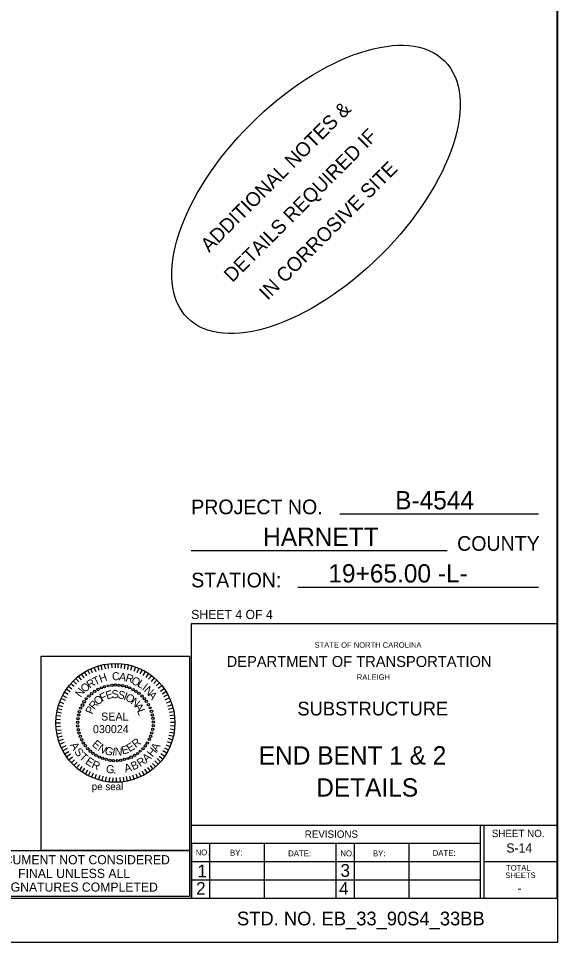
# Model space of a CAD drawing. Extents: x -41 to 251, y -169 to 237.
# Drawn here: x 58.79 to 75.65, y -168.52 to -139.61 of the extents above; entities that cross this region are included whole.
import ezdxf

# ---------------------------------------------------------------- set-up
doc = ezdxf.new("R2010")
doc.units = 0
for name, color, linetype in [('Peseal', 7, 'Continuous'), ('Plan Sheet CELL', 7, 'Continuous'), ('Plot Shape CELL', 7, 'Continuous'), ('Sheet Sticker Exception Certification CELL', 7, 'Continuous'), ('Subtitle Text', 7, 'Continuous'), ('Text', 7, 'Continuous'), ('Title Text', 7, 'Continuous'), ('User Information Notes', 7, 'Continuous'), ('User Information Notes CELL', 7, 'Continuous')]:
    doc.layers.add(name, color=color, linetype=linetype)

msp = doc.modelspace()

# ---------------------------------------------------------------- linework, layer by layer
at = {"layer": 'Peseal'}
for p, q in [((61.31, -160.006), (61.265, -159.863)), ((61.408, -159.98), (61.373, -159.836)), ((61.507, -159.953), (61.48, -159.81)), ((61.605, -159.944), (61.587, -159.801)), ((61.713, -159.926), (61.704, -159.783)), ((61.82, -159.926), (61.82, -159.783)), ((61.9, -159.926), (61.909, -159.783)), ((61.999, -159.935), (62.017, -159.792)), ((62.106, -159.953), (62.124, -159.81)), ((62.205, -159.971), (62.231, -159.828)), ((62.303, -159.997), (62.339, -159.854)), ((60.836, -160.23), (60.755, -160.114)), ((60.925, -160.176), (60.854, -160.051)), ((61.015, -160.123), (60.952, -159.997)), ((61.104, -160.078), (61.051, -159.953)), ((61.212, -160.042), (61.158, -159.908)), ((62.401, -160.024), (62.455, -159.89)), ((62.5, -160.069), (62.562, -159.935)), ((62.598, -160.114), (62.661, -159.98)), ((62.688, -160.158), (62.759, -160.033)), ((62.777, -160.221), (62.858, -160.096)), ((60.532, -160.507), (60.424, -160.418)), ((60.603, -160.436), (60.496, -160.328)), ((60.675, -160.364), (60.585, -160.257)), ((60.755, -160.293), (60.666, -160.185)), ((62.858, -160.275), (62.947, -160.167)), ((62.947, -160.346), (63.036, -160.239)), ((63.019, -160.409), (63.117, -160.311)), ((63.09, -160.489), (63.198, -160.391)), ((60.344, -160.758), (60.219, -160.686)), ((60.407, -160.668), (60.281, -160.588)), ((60.46, -160.588), (60.353, -160.507)), ((63.153, -160.561), (63.269, -160.472)), ((63.224, -160.65), (63.341, -160.57)), ((63.278, -160.731), (63.394, -160.659)), ((60.21, -161.044), (60.076, -160.99)), ((60.254, -160.946), (60.12, -160.883)), ((60.299, -160.856), (60.165, -160.785)), ((63.332, -160.82), (63.457, -160.758)), ((63.376, -160.919), (63.502, -160.856)), ((63.421, -161.017), (63.555, -160.964)), ((60.147, -161.241), (60.013, -161.205)), ((60.174, -161.142), (60.04, -161.098)), ((63.457, -161.116), (63.591, -161.071)), ((63.484, -161.214), (63.618, -161.178)), ((63.502, -161.312), (63.645, -161.286)), ((60.102, -161.545), (59.959, -161.536)), ((60.111, -161.438), (59.977, -161.42)), ((60.129, -161.339), (59.986, -161.312)), ((63.52, -161.411), (63.663, -161.393)), ((63.528, -161.509), (63.672, -161.5)), ((60.102, -161.652), (59.959, -161.652)), ((60.102, -161.76), (59.959, -161.769)), ((60.12, -161.867), (59.977, -161.885)), ((63.528, -161.831), (63.672, -161.849)), ((63.537, -161.617), (63.681, -161.617)), ((63.537, -161.724), (63.681, -161.733)), ((60.129, -161.965), (59.995, -161.992)), ((60.156, -162.064), (60.013, -162.1)), ((60.183, -162.162), (60.049, -162.207)), ((63.466, -162.126), (63.609, -162.171)), ((63.493, -162.028), (63.636, -162.064)), ((63.511, -161.93), (63.654, -161.957)), ((60.219, -162.261), (60.085, -162.314)), ((60.263, -162.359), (60.129, -162.422)), ((60.308, -162.449), (60.174, -162.52)), ((63.35, -162.422), (63.484, -162.484)), ((63.394, -162.332), (63.528, -162.386)), ((63.439, -162.225), (63.573, -162.279)), ((60.362, -162.547), (60.237, -162.618)), ((60.415, -162.627), (60.299, -162.708)), ((60.478, -162.717), (60.362, -162.806)), ((63.189, -162.681), (63.305, -162.771)), ((63.242, -162.601), (63.367, -162.681)), ((63.305, -162.511), (63.43, -162.583)), ((60.541, -162.797), (60.442, -162.887)), ((60.621, -162.869), (60.514, -162.976)), ((60.693, -162.941), (60.603, -163.048)), ((60.773, -163.012), (60.693, -163.119)), ((62.822, -163.039), (62.902, -163.155)), ((62.902, -162.976), (62.992, -163.093)), ((62.983, -162.914), (63.072, -163.012)), ((63.054, -162.833), (63.162, -162.941)), ((63.126, -162.762), (63.233, -162.86)), ((60.854, -163.066), (60.773, -163.182)), ((60.943, -163.119), (60.872, -163.245)), ((61.033, -163.173), (60.97, -163.298)), ((61.122, -163.218), (61.069, -163.343)), ((61.221, -163.254), (61.176, -163.388)), ((61.328, -163.289), (61.283, -163.424)), ((61.426, -163.316), (61.391, -163.45)), ((61.525, -163.334), (61.498, -163.477)), ((62.16, -163.325), (62.187, -163.468)), ((62.258, -163.307), (62.294, -163.441)), ((62.357, -163.271), (62.401, -163.415)), ((62.455, -163.236), (62.509, -163.37)), ((62.553, -163.2), (62.616, -163.325)), ((62.643, -163.146), (62.714, -163.28)), ((62.732, -163.093), (62.813, -163.218)), ((61.632, -163.352), (61.614, -163.495)), ((61.739, -163.361), (61.73, -163.504)), ((61.847, -163.361), (61.847, -163.504)), ((61.954, -163.352), (61.963, -163.495)), ((62.061, -163.343), (62.079, -163.486))]:
    msp.add_line(p, q, dxfattribs=at)
for centre, radius in [((61.708, -160.472), 0.0361), ((61.82, -160.463), 0.0358), ((61.932, -160.472), 0.0361), ((62.044, -160.481), 0.0369), ((61.073, -160.727), 0.0385), ((61.171, -160.655), 0.0385), ((61.274, -160.597), 0.04), ((61.377, -160.548), 0.0341), ((61.48, -160.512), 0.0326), ((61.592, -160.485), 0.0316), ((62.16, -160.512), 0.0326), ((62.263, -160.548), 0.0341), ((62.366, -160.601), 0.0361), ((62.464, -160.655), 0.0361), ((62.558, -160.722), 0.0349), ((60.84, -160.986), 0.0385), ((60.903, -160.888), 0.0316), ((60.988, -160.803), 0.038), ((62.647, -160.803), 0.0349), ((62.723, -160.888), 0.0349), ((62.79, -160.973), 0.0361), ((60.693, -161.29), 0.0382), ((60.733, -161.183), 0.0341), ((60.787, -161.089), 0.0412), ((62.853, -161.071), 0.0361), ((62.907, -161.174), 0.0341), ((62.947, -161.281), 0.0382), ((60.639, -161.626), 0.0358), ((60.648, -161.514), 0.0361), ((60.666, -161.402), 0.0369), ((62.974, -161.393), 0.0369), ((62.992, -161.505), 0.0361), ((63.001, -161.617), 0.0358), ((60.639, -161.737), 0.0361), ((60.657, -161.854), 0.0361), ((62.983, -161.845), 0.0361), ((63.001, -161.728), 0.0361), ((60.684, -161.965), 0.0369), ((60.72, -162.068), 0.0382), ((60.764, -162.171), 0.04), ((62.88, -162.162), 0.0361), ((62.92, -162.068), 0.0382), ((62.956, -161.957), 0.0369), ((60.814, -162.27), 0.0361), ((60.881, -162.355), 0.0349), ((60.952, -162.449), 0.038), ((62.679, -162.453), 0.0349), ((62.755, -162.364), 0.0385), ((62.817, -162.27), 0.0361), ((61.033, -162.529), 0.038), ((61.118, -162.596), 0.0385), ((61.212, -162.659), 0.0361), ((61.314, -162.712), 0.0341), ((61.422, -162.753), 0.0382), ((61.534, -162.788), 0.0369), ((62.097, -162.788), 0.0369), ((62.209, -162.757), 0.0341), ((62.312, -162.717), 0.04), ((62.419, -162.659), 0.0361), ((62.513, -162.601), 0.0349), ((62.594, -162.529), 0.0349), ((61.645, -162.815), 0.0361), ((61.757, -162.824), 0.0358), ((61.874, -162.824), 0.0358), ((61.985, -162.815), 0.0361)]:
    msp.add_circle(centre, radius, dxfattribs=at)
at = {"layer": 'Plan Sheet CELL'}
for p, q in [((75.628, -119.081), (75.628, -167.129)), ((75.057, -155.116), (68.84, -155.116)), ((72.197, -156.26), (64.189, -156.26)), ((75.057, -157.404), (67.53, -157.404)), ((75.628, -158.548), (64.189, -158.548)), ((64.189, -158.548), (64.189, -167.129)), ((64.189, -164.84), (75.628, -164.84)), ((73.227, -164.84), (73.227, -167.129)), ((73.341, -164.84), (73.341, -167.129)), ((64.189, -165.411), (73.231, -165.411)), ((64.196, -165.411), (64.196, -167.129)), ((64.76, -165.411), (64.76, -167.129)), ((66.476, -165.421), (66.476, -167.137)), ((68.709, -165.411), (68.709, -167.143)), ((69.282, -165.411), (69.282, -167.13)), ((70.998, -165.411), (70.998, -167.13)), ((64.189, -165.984), (73.25, -165.984)), ((73.341, -165.984), (75.608, -165.984)), ((64.189, -166.556), (73.231, -166.556)), ((2.412, -167.129), (75.628, -167.129)), ((75.648, -168.516), (75.648, -168.516))]:
    msp.add_line(p, q, dxfattribs=at)
at = {"layer": 'Plot Shape CELL'}
msp.add_lwpolyline([(0, -118.18), (75.648, -118.18), (75.648, -168.516), (0, -168.516)], close=True, dxfattribs=at)
at = {"layer": 'Sheet Sticker Exception Certification CELL'}
msp.add_lwpolyline([(57.615, -165.636), (64.139, -165.636), (64.139, -167.071), (57.615, -167.071)], close=True, dxfattribs=at)
at = {"layer": 'User Information Notes'}
msp.add_line((61.82, -161.643), (61.82, -161.643), dxfattribs=at)
msp.add_ellipse((68.093, -144.954), major_axis=(4.02, 4.02), ratio=0.508254, dxfattribs=at)
at = {"layer": 'User Information Notes CELL'}
msp.add_line((61.82, -161.643), (61.82, -161.643), dxfattribs=at)
msp.add_lwpolyline([(59.501, -159.554), (64.139, -159.554), (64.139, -165.636), (59.501, -165.636)], close=True, dxfattribs=at)
msp.add_circle((61.82, -161.643), 1.861, dxfattribs=at)

# ---------------------------------------------------------------- texts
at = {"layer": 'Peseal'}
for s, height, rotation, p in [('H', 0.25, 18.9162, (61.355, -160.391)), ('C', 0.25, 4.8625, (61.722, -160.32)), ('A', 0.25, 350.8088, (61.918, -160.311)), ('R', 0.25, 343.7819, (62.115, -160.337)), ('O', 0.25, 39.9967, (60.854, -160.713)), ('R', 0.25, 32.9699, (61.015, -160.579)), ('T', 0.25, 25.943, (61.185, -160.481)), ('O', 0.25, 336.7551, (62.294, -160.409)), ('L', 0.25, 329.7282, (62.482, -160.489)), ('I', 0.25, 322.7014, (62.634, -160.588)), ('N', 0.25, 54.0504, (60.738, -160.865)), ('F', 0.25, 26.4777, (61.399, -160.99)), ('E', 0.25, 18.4448, (61.56, -160.919)), ('S', 0.25, 2.3789, (61.704, -160.874)), ('S', 0.25, 346.313, (61.874, -160.865)), ('I', 0.25, 338.28, (62.052, -160.91)), ('N', 0.25, 315.6745, (62.697, -160.642)), ('A', 0.25, 308.6477, (62.822, -160.776)), ('R', 0.25, 50.5765, (61.158, -161.25)), ('O', 0.25, 42.5436, (61.274, -161.107)), ('O', 0.25, 330.2471, (62.106, -160.919)), ('N', 0.25, 322.2141, (62.276, -161.026)), ('P', 0.25, 66.6424, (61.095, -161.393)), ('A', 0.25, 306.1483, (62.401, -161.134)), ('L', 0.25, 290.0824, (62.491, -161.259)), ('E', 0.25, 318.5179, (61.069, -162.341)), ('R', 0.25, 38.6997, (62.455, -162.44)), ('A', 0.254, 300.3993, (60.389, -162.338)), ('S', 0.254, 309.4349, (60.516, -162.554)), ('N', 0.25, 326.5361, (61.247, -162.493)), ('G', 0.25, 342.5725, (61.462, -162.61)), ('I', 0.25, 350.5906, (61.704, -162.663)), ('N', 0.25, 358.6088, (61.793, -162.663)), ('E', 0.25, 14.6452, (62.044, -162.636)), ('E', 0.25, 30.6815, (62.258, -162.565)), ('H', 0.254, 51.3597, (62.98, -162.731)), ('A', 0.254, 59.6007, (63.124, -162.553)), ('T', 0.254, 318.1096, (60.668, -162.74)), ('E', 0.254, 327.1453, (60.855, -162.907)), ('R', 0.254, 33.5776, (62.593, -163.033)), ('A', 0.254, 42.3241, (62.795, -162.9)), ('R', 0.254, 335.458, (61.048, -163.034)), ('G', 0.254, 353.3858, (61.513, -163.204)), ('A', 0.254, 15.7955, (62.131, -163.203)), ('B', 0.254, 24.8312, (62.372, -163.135)), ('.', 0.254, 2.1323, (61.754, -163.232))]:
    msp.add_text(s, height=height, rotation=rotation, dxfattribs=at).set_placement(p)
for s, p in [('SEAL', (61.373, -161.572)), ('030024', (61.116, -161.965))]:
    msp.add_text(s, height=0.2505, dxfattribs=at).set_placement(p)
at = {"layer": 'Plan Sheet CELL'}
for s, height, p in [('PROJECT NO.', 0.4576, (64.189, -155.116)), ('COUNTY', 0.4576, (72.508, -156.26)), ('STATION:', 0.4576, (64.189, -157.404)), ('SHEET 4 OF 4', 0.286, (64.189, -158.395)), ('STATE OF NORTH CAROLINA', 0.17159, (68.049, -159.292)), ('DEPARTMENT OF TRANSPORTATION', 0.34319, (65.298, -159.895)), ('RALEIGH', 0.1716, (69.37, -160.297)), ('REVISIONS', 0.2288, (67.741, -165.239)), ('SHEET NO.', 0.2288, (73.593, -165.217)), ('NO.', 0.1823, (64.325, -165.789)), ('BY:', 0.1823, (65.405, -165.797)), ('DATE:', 0.1823, (67.222, -165.817)), ('NO.', 0.1823, (68.855, -165.817)), ('BY:', 0.1823, (69.876, -165.819)), ('DATE:', 0.1823, (71.742, -165.807)), ('1', 0.4, (64.384, -166.479)), ('3', 0.4, (68.859, -166.46)), ('TOTAL', 0.1716, (74.041, -166.266)), ('SHEETS', 0.1716, (74.015, -166.497)), ('2', 0.4, (64.343, -167.023)), ('4', 0.4, (68.816, -167.023))]:
    msp.add_text(s, height=height, dxfattribs=at).set_placement(p)
at = {"layer": 'Sheet Sticker Exception Certification CELL'}
for s, p in [('DOCUMENT NOT CONSIDERED', (57.75, -166.068)), ('FINAL UNLESS ALL', (58.776, -166.496)), ('SIGNATURES COMPLETED', (58.181, -166.924))]:
    msp.add_text(s, height=0.28561, dxfattribs=at).set_placement(p)
at = {"layer": 'Subtitle Text'}
for s, p in [('SUBSTRUCTURE', (67.511, -161.412)), ('STD. NO. EB_33_90S4_33BB', (65.622, -167.979))]:
    msp.add_text(s, height=0.429, dxfattribs=at).set_placement(p)
at = {"layer": 'Text'}
for s, p in [('S-14', (74.048, -165.7)), ('-', (74.396, -166.959))]:
    msp.add_text(s, height=0.286, dxfattribs=at).set_placement(p)
at = {"layer": 'Title Text'}
for s, p in [('B-4544', (70.57, -154.963)), ('HARNETT', (66.44, -156.108)), ('19+65.00 -L-', (68.48, -157.252)), ('END BENT 1 & 2', (66.304, -162.947)), ('DETAILS', (68.1, -163.95))]:
    msp.add_text(s, height=0.572, dxfattribs=at).set_placement(p)
at = {"layer": 'User Information Notes'}
for s, p in [('ADDITIONAL NOTES &', (64.752, -146.948)), ('DETAILS REQUIRED IF', (65.475, -147.885)), ('IN CORROSIVE SITE', (66.579, -148.442))]:
    msp.add_text(s, height=0.44304, rotation=45, dxfattribs=at).set_placement(p)
at = {"layer": 'User Information Notes CELL'}
msp.add_text('pe seal', height=0.229, dxfattribs=at).set_placement((61.078, -163.748))

doc.saveas('drawing.dxf')
